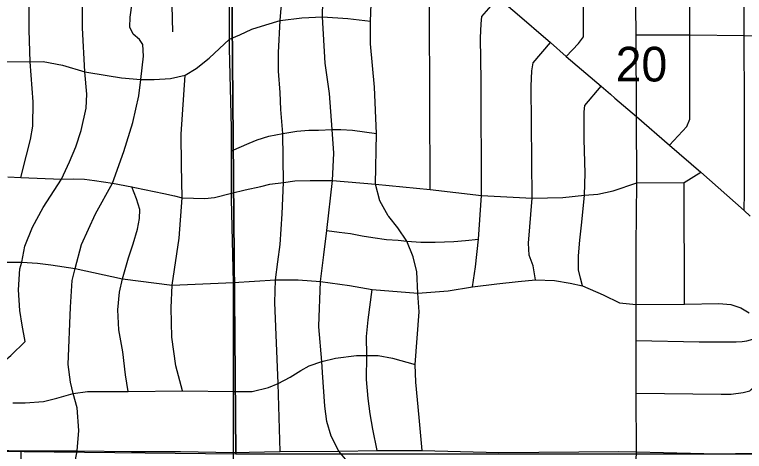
# Model space of a CAD drawing. Extents: x 0 to 34, y 0 to 22.
# Drawn here: x 3.784 to 4.664, y 19.505 to 20.032 of the extents above; entities that cross this region are included whole.
import ezdxf

# ---------------------------------------------------------------- set-up
doc = ezdxf.new("R2010")
doc.units = 0
for name, color, linetype in [('GM_X_City_Street', 7, 'Continuous'), ('GM_X_County_Road', 7, 'Continuous'), ('GM_X_Section', 7, 'Continuous'), ('GM_X_Section_Text', 7, 'Continuous')]:
    doc.layers.add(name, color=color, linetype=linetype)

msp = doc.modelspace()

# ---------------------------------------------------------------- linework, layer by layer
at = {"layer": 'GM_X_City_Street'}
msp.add_line((4.59194, 19.68278), (4.59187, 19.82928), dxfattribs=at)
for points in [[(4.57415, 19.87448), (4.59509, 19.89694), (4.59866, 19.90586), (4.59863, 20.00748), (4.59856, 20.23422), (4.59781, 20.26754), (4.5971, 20.29155), (4.5964, 20.30144), (4.5964, 20.30991), (4.60063, 20.32191), (4.60486, 20.33392), (4.6098, 20.35227), (4.61, 20.51056)], [(4.66429, 19.79557), (4.66462, 19.8171), (4.66462, 19.92074), (4.66414, 20.0067), (4.66474, 20.20814), (4.67143, 20.23007), (4.67468, 20.24016), (4.67648, 20.25384), (4.6772, 20.26428), (4.67756, 20.27401), (4.67612, 20.28265), (4.67395, 20.29742), (4.67179, 20.31578), (4.67, 20.33703), (4.66941, 20.35034), (4.6692, 20.51025)], [(3.79153, 19.83525), (3.7983, 19.86236), (3.80319, 19.88119), (3.80598, 19.89724), (3.80667, 19.92653), (3.80295, 19.97468), (3.80179, 20.01303), (3.80179, 20.13463), (3.80079, 20.26548), (3.80014, 20.37132), (3.82139, 20.40555)], [(3.79672, 19.63776), (3.79329, 19.65724), (3.79024, 19.67478), (3.78871, 19.69996), (3.79024, 19.72515), (3.79269, 19.73335), (3.79634, 19.75261), (3.8055, 19.7755), (3.81847, 19.79916), (3.84052, 19.83329), (3.85052, 19.85409), (3.85815, 19.87241), (3.86425, 19.89225), (3.87035, 19.91895), (3.87111, 19.93574), (3.86876, 19.96283), (3.86617, 20.01581), (3.86522, 20.1349), (3.86514, 20.14694), (3.86441, 20.26662), (3.86331, 20.3245), (3.88735, 20.36326)], [(3.97489, 20.01111), (3.97274, 20.1072), (3.97181, 20.31036)], [(4.44937, 19.98149), (4.46416, 19.99717), (4.47045, 20.00519), (4.4708, 20.14558), (4.46987, 20.25729)], [(4.27577, 19.50611), (4.27225, 19.54581), (4.2679, 19.58851), (4.26721, 19.60986), (4.27225, 19.67321), (4.27033, 19.69603), (4.26935, 19.72171), (4.26501, 19.7398), (4.25705, 19.75863), (4.24619, 19.77455), (4.23533, 19.7883), (4.2346, 19.78903), (4.22447, 19.80712), (4.21939, 19.8273), (4.22067, 19.8886), (4.21825, 19.94416), (4.21342, 19.99649), (4.21342, 20.02387), (4.21503, 20.06573), (4.21745, 20.08506), (4.22711, 20.11565), (4.24098, 20.14131)], [(4.10439, 19.50509), (4.10217, 19.58686), (4.09811, 19.68467), (4.09886, 19.71206), (4.10142, 19.73366), (4.10435, 19.75474), (4.10669, 19.79161), (4.10851, 19.82947), (4.10784, 19.88854), (4.1054, 19.91726), (4.10427, 19.938), (4.10239, 19.96365), (4.10239, 19.98628), (4.10435, 20.02469), (4.10556, 20.03957), (4.10781, 20.04923), (4.11263, 20.06049), (4.1181, 20.06917), (4.12583, 20.07673), (4.13339, 20.08365), (4.13998, 20.08847), (4.14963, 20.09812), (4.16127, 20.10876)], [(4.28551, 19.82092), (4.28511, 19.92937), (4.28441, 20.03496), (4.2837, 20.06826), (4.28442, 20.07461), (4.30239, 20.10099)], [(4.21534, 19.44926), (4.20947, 19.46187), (4.19338, 19.48352), (4.17513, 19.50518), (4.16591, 19.52327), (4.16076, 19.54117), (4.15845, 19.55941), (4.15556, 19.60002), (4.1545, 19.61367), (4.15125, 19.6552), (4.15125, 19.65606), (4.15323, 19.70997), (4.15729, 19.74229), (4.16073, 19.77161), (4.16742, 19.83163), (4.16936, 19.86473), (4.16715, 19.89331), (4.16377, 19.93656), (4.1588, 19.97307), (4.15568, 20.0293), (4.1563, 20.06684)], [(3.85617, 19.48857), (3.85954, 19.50588), (3.86161, 19.53033), (3.8596, 19.55746), (3.85464, 19.5749), (3.85157, 19.58861), (3.84855, 19.60971), (3.85157, 19.67904), (3.85357, 19.71119), (3.85697, 19.72579), (3.86463, 19.75439), (3.88171, 19.79157), (3.90237, 19.82854), (3.91601, 19.86692), (3.92671, 19.90186), (3.93384, 19.93394), (3.93654, 19.95362), (3.93955, 19.98171), (3.93877, 19.99562), (3.93461, 20.00187), (3.92711, 20.00807), (3.92315, 20.01671), (3.92341, 20.02869), (3.92776, 20.06096)], [(4.33654, 19.7037), (4.34021, 19.72774), (4.34355, 19.76111), (4.34715, 19.81367), (4.34688, 19.95214), (4.34605, 20.00386), (4.34688, 20.02055), (4.34772, 20.02972), (4.3673, 20.05252)], [(3.77268, 19.97534), (3.80295, 19.97468), (3.81874, 19.97534), (3.84178, 19.97072), (3.86876, 19.96283), (3.89574, 19.95822), (3.91285, 19.95559), (3.93654, 19.95362), (3.95233, 19.95362), (3.97207, 19.95493), (3.98985, 19.95888), (4.00301, 19.96678), (4.0188, 19.97928), (4.04338, 20.00232), (4.05565, 20.00758), (4.07013, 20.01416), (4.08724, 20.01942), (4.10435, 20.02469), (4.13067, 20.02798), (4.15568, 20.0293), (4.18595, 20.02732), (4.21342, 20.02387)], [(4.53381, 20.00735), (4.59863, 20.00748), (4.66414, 20.0067), (4.73028, 20.00576), (4.80936, 20.00632), (4.86993, 20.0052), (5.02378, 20.00254), (5.19599, 19.99843), (5.31313, 19.99746), (5.32195, 19.99843), (5.33224, 20.00235), (5.36557, 20.01997)], [(4.41251, 19.71206), (4.40943, 19.72893), (4.40462, 19.74177), (4.40382, 19.75621), (4.40847, 19.81033), (4.40703, 19.94554), (4.40783, 19.96399), (4.40943, 19.97362), (4.4305, 19.99803)], [(3.98677, 19.57806), (3.97851, 19.60824), (3.97389, 19.64283), (3.97279, 19.67838), (3.97419, 19.70562), (3.98254, 19.76219), (3.98612, 19.81093), (3.98562, 19.85032), (3.98489, 19.88761), (3.98985, 19.95888)], [(4.46926, 19.7047), (4.4665, 19.71384), (4.46424, 19.72402), (4.46424, 19.74098), (4.46594, 19.75964), (4.4682, 19.78169), (4.47146, 19.81423), (4.47216, 19.84049), (4.47103, 19.8812), (4.47103, 19.91455), (4.47195, 19.92211), (4.49154, 19.9455)], [(4.04579, 19.8674), (4.06694, 19.87661), (4.07682, 19.8807), (4.09079, 19.88513), (4.10784, 19.88854), (4.12454, 19.89126), (4.1392, 19.89263), (4.15079, 19.89263), (4.16715, 19.89331), (4.17771, 19.89331), (4.19168, 19.89229), (4.22067, 19.8886)], [(3.77614, 19.83624), (3.79153, 19.83525), (3.84052, 19.83329), (3.85479, 19.83377), (3.86859, 19.83329), (3.88049, 19.83187), (3.90237, 19.82854), (3.92548, 19.82399), (3.92903, 19.8233), (3.96424, 19.81617), (3.97708, 19.81331), (3.98612, 19.81093), (4.01372, 19.80998), (4.02515, 19.81141), (4.04579, 19.81664), (4.06217, 19.82037), (4.08123, 19.8247), (4.09205, 19.8273), (4.10851, 19.82947), (4.12194, 19.8312), (4.14056, 19.83163), (4.16742, 19.83163), (4.21939, 19.8273), (4.28551, 19.82092), (4.34715, 19.81367), (4.40847, 19.81033), (4.44527, 19.81144), (4.47146, 19.81423), (4.48763, 19.81534), (4.50602, 19.81925), (4.53473, 19.82898), (4.59187, 19.82928), (4.61176, 19.84168)], [(3.9211, 19.57727), (3.91797, 19.59728), (3.9145, 19.62496), (3.90989, 19.65148), (3.90874, 19.6757), (3.91047, 19.69704), (3.91432, 19.71318), (3.92143, 19.73855), (3.92719, 19.75527), (3.93238, 19.77315), (3.93469, 19.78583), (3.93526, 19.79678), (3.93123, 19.80947), (3.92548, 19.82399)], [(4.16073, 19.77161), (4.17578, 19.76964), (4.1893, 19.76802), (4.20338, 19.76504), (4.21609, 19.76287), (4.23287, 19.76071), (4.24694, 19.75963), (4.25705, 19.75863), (4.27427, 19.75746), (4.29132, 19.75719), (4.31378, 19.758), (4.32785, 19.75935), (4.34355, 19.76111)], [(3.77441, 19.73335), (3.79269, 19.73335), (3.81159, 19.73209), (3.82798, 19.7302), (3.85697, 19.72579), (3.91432, 19.71318), (3.97419, 19.70562), (4.04818, 19.70868), (4.09886, 19.71206), (4.12605, 19.71206), (4.15323, 19.70997), (4.18808, 19.7051), (4.2155, 19.70041), (4.27033, 19.69603), (4.30727, 19.69882), (4.33654, 19.7037), (4.36581, 19.70718), (4.3916, 19.70997), (4.41251, 19.71206), (4.43551, 19.71136), (4.45433, 19.70788), (4.46926, 19.7047), (4.49406, 19.69394), (4.51357, 19.68419), (4.53398, 19.68236), (4.59194, 19.68278), (4.63375, 19.68345), (4.64791, 19.6821), (4.66005, 19.67806), (4.67016, 19.67199)], [(4.22153, 19.5061), (4.21624, 19.53196), (4.21308, 19.55051), (4.21071, 19.56867), (4.20874, 19.59196), (4.2091, 19.62079), (4.20874, 19.64366), (4.21071, 19.66379), (4.2155, 19.70041)], [(4.53402, 19.57542), (4.63636, 19.57409), (4.64842, 19.57409), (4.66283, 19.57612), (4.67085, 19.57824), (4.67272, 19.5798), (4.68086, 19.58659), (4.68889, 19.59242), (4.71063, 19.60523), (4.80226, 19.66684)], [(4.534, 19.63893), (4.60965, 19.6373), (4.63641, 19.6373), (4.65436, 19.6373), (4.66187, 19.63763), (4.66742, 19.63828), (4.67446, 19.64029), (4.6795, 19.64416), (4.685, 19.64906)], [(3.74062, 19.59399), (3.75297, 19.60061), (3.7637, 19.60804), (3.77939, 19.6207), (3.79672, 19.63776)], [(3.78185, 19.56382), (3.7953, 19.56382), (3.79688, 19.56382), (3.81904, 19.56541), (3.83486, 19.56936), (3.85464, 19.5749), (3.87205, 19.57727), (3.9211, 19.57727), (3.98677, 19.57806), (4.04819, 19.57727), (4.07064, 19.57727), (4.09041, 19.58202), (4.10217, 19.58686), (4.11652, 19.59468), (4.12918, 19.60259), (4.13947, 19.60813), (4.1545, 19.61367), (4.17112, 19.61763), (4.19643, 19.62079), (4.2091, 19.62079), (4.22254, 19.62079), (4.23995, 19.61763), (4.26721, 19.60986)], [(3.55615, 19.50881), (3.61303, 19.50805), (3.6739, 19.50718), (3.73172, 19.50718), (3.79215, 19.50588), (3.85954, 19.50588), (3.92519, 19.50501), (3.98431, 19.50501), (4.04819, 19.5037), (4.10439, 19.50509), (4.17513, 19.50518), (4.22153, 19.5061), (4.27577, 19.50611), (4.36805, 19.50372), (4.51295, 19.50505), (4.53405, 19.50437), (4.63184, 19.50201), (4.6753, 19.50298), (4.75176, 19.50458), (4.76019, 19.50475), (4.80108, 19.50436), (4.86718, 19.50405), (4.91274, 19.50445)], [(3.78914, 18.9829), (3.7874, 19.05322), (3.7874, 19.10015), (3.78774, 19.10376), (3.79342, 19.16393), (3.79479, 19.24313), (3.79051, 19.36859), (3.79215, 19.50588)]]:
    msp.add_lwpolyline(points, dxfattribs=at)
at = {"layer": 'GM_X_County_Road'}
for points in [[(4.53444, 19.90889), (4.53381, 20.00735), (4.53233, 20.14542), (4.53235, 20.24866), (4.53261, 20.34749), (4.53274, 20.39959), (4.53289, 20.45598), (4.53176, 20.51228), (4.53229, 20.52328), (4.53515, 20.60078), (4.53515, 20.64463), (4.53516, 20.69542), (4.53516, 20.70693)], [(4.04821, 19.08109), (4.04821, 19.08819), (4.04821, 19.09032), (4.04821, 19.15554), (4.0482, 19.24874), (4.0482, 19.3865), (4.04819, 19.44884), (4.04819, 19.5037), (4.04819, 19.57727), (4.04818, 19.70868), (4.04579, 19.80922), (4.04579, 19.81664), (4.04579, 19.8674), (4.04579, 19.89538), (4.04338, 19.99113), (4.04338, 20.00232), (4.04338, 20.11228), (4.04337, 20.18148), (4.04337, 20.1874), (4.0432, 20.19595), (4.04316, 20.19695)], [(4.27659, 20.11783), (4.28007, 20.11554), (4.30239, 20.10099), (4.32897, 20.08327), (4.34716, 20.06985), (4.3673, 20.05252), (4.38744, 20.0352), (4.4305, 19.99803), (4.44937, 19.98149), (4.49154, 19.9455), (4.50272, 19.93597)], [(4.50272, 19.93597), (4.5083, 19.9312), (4.53444, 19.90889), (4.57415, 19.87448), (4.61176, 19.84168), (4.66429, 19.79557), (4.67144, 19.78891)], [(4.53398, 19.68236), (4.53398, 19.75323), (4.53473, 19.82898), (4.53444, 19.90889)], [(4.53345, 19.48477), (4.53405, 19.50437), (4.53402, 19.57542), (4.534, 19.63893), (4.53398, 19.68236)]]:
    msp.add_lwpolyline(points, dxfattribs=at)
at = {"layer": 'GM_X_Section'}
for points in [[(3.04368, 20.50725), (4.04262, 20.49916), (4.05087, 19.50181), (3.02863, 19.51298)], [(4.04262, 20.49916), (5.03178, 20.49467), (5.03707, 19.50155), (4.05087, 19.50181)]]:
    msp.add_lwpolyline(points, close=True, dxfattribs=at)

# ---------------------------------------------------------------- texts
at = {"layer": 'GM_X_Section_Text'}
msp.add_text('20', height=0.041856, rotation=0.00001, dxfattribs=at).set_placement((4.5091, 19.95116))

doc.saveas('drawing.dxf')
